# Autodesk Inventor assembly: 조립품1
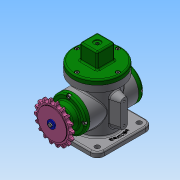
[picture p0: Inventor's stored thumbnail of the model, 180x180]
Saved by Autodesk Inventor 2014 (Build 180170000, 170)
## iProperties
Created: 2021-03
Part Number: 조립품1
Document SubType Name: Assembly
Designer: NET
Author: NET
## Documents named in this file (19)
- C:\Users\NET\Desktop\710306V1020\조립품1.iam
- C:\Users\NET\Desktop\710306V1020\710306V1020.ipt
- C:\Users\NET\Desktop\710306V1020\베어링 17 x 40 x 12.ipt
- C:\Users\NET\Desktop\710306V1020\편심축.ipt
- C:\Users\NET\Desktop\710306V1020\뒤커버.ipt
- C:\Users\NET\Desktop\710306V1020\링크.ipt
- C:\Users\NET\Desktop\710306V1020\슬라이더.ipt
- C:\Users\NET\Desktop\710306V1020\클레비스 핀 6 x 22.ipt
- 클레비스 핀 6 x 22.ipt
- C:\Users\NET\Desktop\710306V1020\E-링.ipt
- C:\Users\NET\Desktop\710306V1020\앞커버.ipt
- C:\Users\NET\Desktop\710306V1020\오일 실 17 30 8.ipt
- C:\Users\NET\Desktop\710306V1020\볼트 M4 x 10.ipt
- C:\Users\NET\Desktop\710306V1020\덮개.ipt
- C:\Users\NET\Desktop\710306V1020\Ű 4 x 4 x 12.ipt
- C:\Users\NET\Desktop\710306V1020\멈춤나사 M3.ipt
- C:\Users\NET\Desktop\710306V1020\스프로킷.ipt
- C:\Users\NET\Desktop\710306V1020\와셔 4x16.ipt
- C:\Users\NET\Desktop\710306V1020\볼트 M4 x 8.ipt
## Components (3 placed, 3 different names)
1. 710306V1020:1
2. E-링:1
3. Ű 4 x 4 x 12:1
